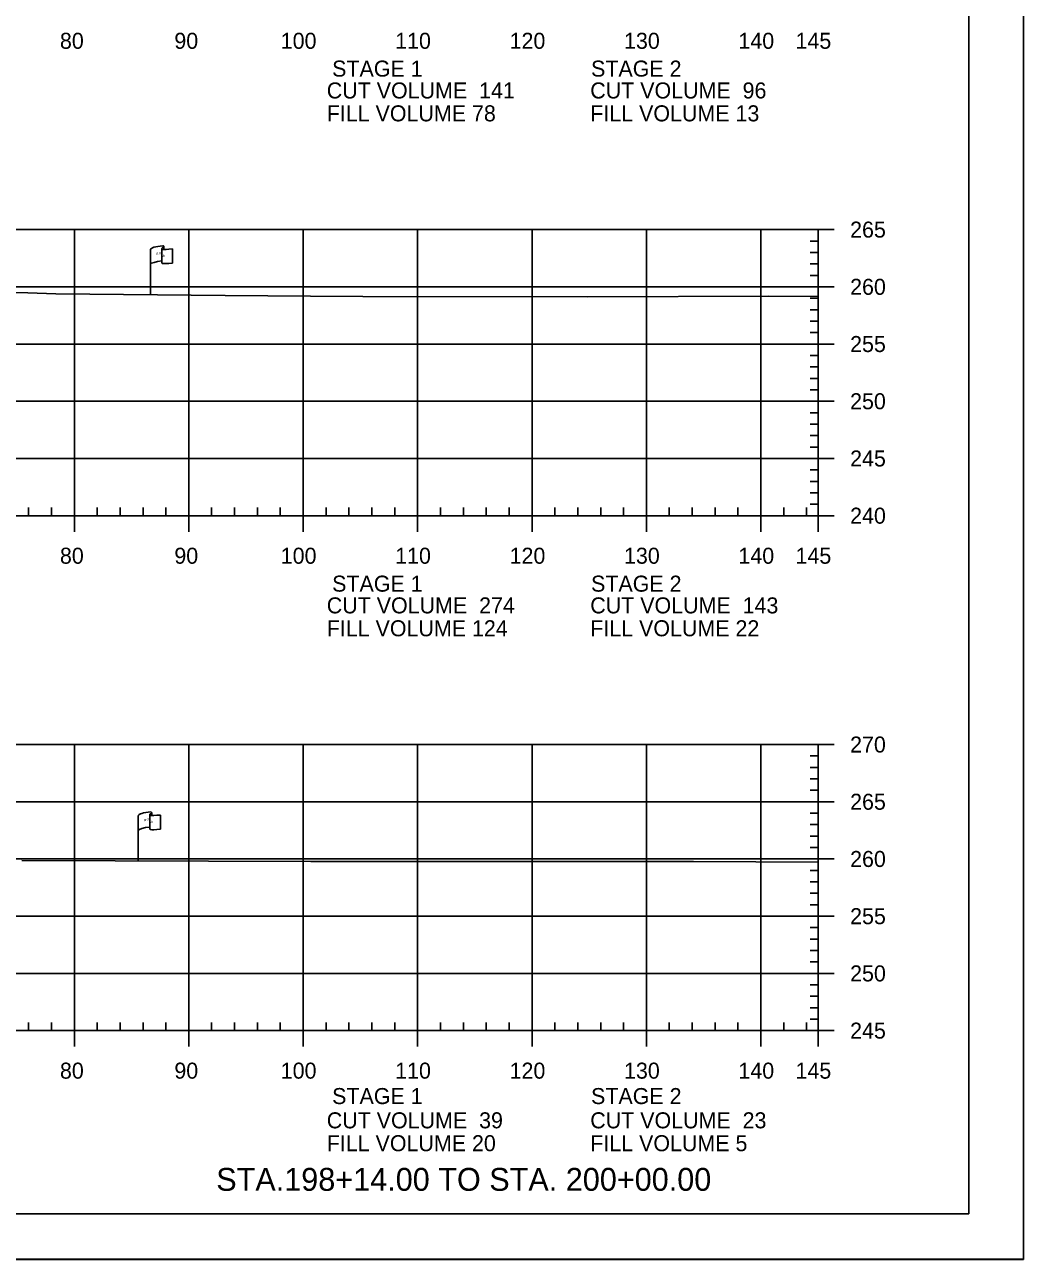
# Model space of a CAD drawing. Extents: x 1365647 to 1367999, y 387113 to 400173.
# Drawn here: x 1365969.7 to 1366057, y 389506.1 to 389614 of the extents above; entities that cross this region are included whole.
import ezdxf

# ---------------------------------------------------------------- set-up
doc = ezdxf.new("R2010")
doc.units = 0
for name, color, linetype in [('E_Existing ROW', 7, 'Continuous'), ('R_Axis', 7, 'Continuous'), ('R_Axis Annot', 7, 'Continuous'), ('R_Border', 7, 'Continuous'), ('R_Draft', 7, 'Continuous'), ('R_Exist Surface', 7, 'Continuous'), ('R_Grid', 7, 'Continuous'), ('R_No Plot', 7, 'Continuous')]:
    doc.layers.add(name, color=color, linetype=linetype)

msp = doc.modelspace()

# ---------------------------------------------------------------- linework, layer by layer
at = {"layer": 'E_Existing ROW'}
for p, q in [((1365980.74, 389590.4), (1365980.74, 389594.36)), ((1365981.74, 389594.45), (1365981.74, 389594.44)), ((1365981.74, 389594.44), (1365981.74, 389593.21)), ((1365981.91, 389594.61), (1365981.91, 389594.37)), ((1365982.68, 389594.41), (1365982.68, 389593.17)), ((1365979.68, 389540.93), (1365979.68, 389544.88)), ((1365980.68, 389544.98), (1365980.68, 389544.96)), ((1365980.68, 389544.96), (1365980.68, 389543.74)), ((1365980.85, 389545.13), (1365980.85, 389544.89)), ((1365981.61, 389544.94), (1365981.61, 389543.7))]:
    msp.add_line(p, q, dxfattribs=at)
for centre, radius, start, end in [((1365981.82, 389594.45), 0.078, 88.6458, 274.2828), ((1365981.83, 389594.61), 0.0783, 263.0712, 93.9564), ((1365981.82, 389593.21), 0.0783, 180, 273.9564), ((1365980.76, 389544.98), 0.078, 88.6458, 274.2828), ((1365980.77, 389545.13), 0.0783, 263.0712, 93.9564), ((1365980.76, 389543.74), 0.0783, 180, 273.9564)]:
    msp.add_arc(centre, radius, start, end, dxfattribs=at)
for centre, major_axis, ratio, start_param, end_param in [((1365982.33, 389594.4), (-1.58, -0.04), 0.19887, 5.030368, 6.283185), ((1365983.03, 389594.51), (-1.23, -0.13), 0.052933, 0.159456, 1.268315), ((1365982.32, 389593.08), (-1.58, -0.04), 0.19887, 5.083035, 6.194897), ((1365983.03, 389593.27), (-1.23, -0.13), 0.052933, 0.159456, 1.268315), ((1365981.27, 389544.93), (-1.58, -0.04), 0.19887, 5.030368, 6.283185), ((1365981.97, 389545.04), (-1.23, -0.13), 0.052933, 0.159456, 1.268315), ((1365981.26, 389543.61), (-1.58, -0.04), 0.19887, 5.083035, 6.194897), ((1365981.97, 389543.8), (-1.23, -0.13), 0.052933, 0.159456, 1.268315)]:
    msp.add_ellipse(centre, major_axis=major_axis, ratio=ratio, start_param=start_param, end_param=end_param, dxfattribs=at)
at = {"layer": 'R_Axis'}
for p, q in [((1366039.09, 389571.1), (1366039.09, 389596.1)), ((1366040.49, 389596.1), (1366039.09, 389596.1)), ((1366039.09, 389595.1), (1366038.39, 389595.1)), ((1366039.09, 389594.1), (1366038.39, 389594.1)), ((1366039.09, 389593.1), (1366038.39, 389593.1)), ((1366039.09, 389592.1), (1366038.39, 389592.1)), ((1366039.09, 389590.1), (1366038.39, 389590.1)), ((1366040.49, 389591.1), (1366039.09, 389591.1)), ((1366039.09, 389589.1), (1366038.39, 389589.1)), ((1366039.09, 389588.1), (1366038.39, 389588.1)), ((1366039.09, 389587.1), (1366038.39, 389587.1)), ((1366040.49, 389586.1), (1366039.09, 389586.1)), ((1366039.09, 389585.1), (1366038.39, 389585.1)), ((1366039.09, 389584.1), (1366038.39, 389584.1)), ((1366039.09, 389583.1), (1366038.39, 389583.1)), ((1366039.09, 389582.1), (1366038.39, 389582.1)), ((1366040.49, 389581.1), (1366039.09, 389581.1)), ((1366039.09, 389580.1), (1366038.39, 389580.1)), ((1366039.09, 389579.1), (1366038.39, 389579.1)), ((1366039.09, 389578.1), (1366038.39, 389578.1)), ((1366039.09, 389577.1), (1366038.39, 389577.1)), ((1366040.49, 389576.1), (1366039.09, 389576.1)), ((1366039.09, 389575.1), (1366038.39, 389575.1)), ((1366039.09, 389574.1), (1366038.39, 389574.1)), ((1366039.09, 389573.1), (1366038.39, 389573.1)), ((1365970.09, 389571.1), (1365970.09, 389571.8)), ((1365972.09, 389571.1), (1365972.09, 389571.8)), ((1365976.09, 389571.1), (1365976.09, 389571.8)), ((1365978.09, 389571.1), (1365978.09, 389571.8)), ((1365980.09, 389571.1), (1365980.09, 389571.8)), ((1365982.09, 389571.1), (1365982.09, 389571.8)), ((1365986.09, 389571.1), (1365986.09, 389571.8)), ((1365988.09, 389571.1), (1365988.09, 389571.8)), ((1365990.09, 389571.1), (1365990.09, 389571.8)), ((1365992.09, 389571.1), (1365992.09, 389571.8)), ((1365996.09, 389571.1), (1365996.09, 389571.8)), ((1365998.09, 389571.1), (1365998.09, 389571.8)), ((1366000.09, 389571.1), (1366000.09, 389571.8)), ((1366002.09, 389571.1), (1366002.09, 389571.8)), ((1366006.09, 389571.1), (1366006.09, 389571.8)), ((1366008.09, 389571.1), (1366008.09, 389571.8)), ((1366010.09, 389571.1), (1366010.09, 389571.8)), ((1366012.09, 389571.1), (1366012.09, 389571.8)), ((1366016.09, 389571.1), (1366016.09, 389571.8)), ((1366018.09, 389571.1), (1366018.09, 389571.8)), ((1366020.09, 389571.1), (1366020.09, 389571.8)), ((1366022.09, 389571.1), (1366022.09, 389571.8)), ((1366026.09, 389571.1), (1366026.09, 389571.8)), ((1366028.09, 389571.1), (1366028.09, 389571.8)), ((1366030.09, 389571.1), (1366030.09, 389571.8)), ((1366032.09, 389571.1), (1366032.09, 389571.8)), ((1366036.09, 389571.1), (1366036.09, 389571.8)), ((1366038.09, 389571.1), (1366038.09, 389571.8)), ((1366039.09, 389572.1), (1366038.39, 389572.1)), ((1365749.09, 389571.1), (1366039.09, 389571.1)), ((1365974.09, 389569.7), (1365974.09, 389571.1)), ((1365984.09, 389569.7), (1365984.09, 389571.1)), ((1365994.09, 389569.7), (1365994.09, 389571.1)), ((1366004.09, 389569.7), (1366004.09, 389571.1)), ((1366014.09, 389569.7), (1366014.09, 389571.1)), ((1366024.09, 389569.7), (1366024.09, 389571.1)), ((1366034.09, 389569.7), (1366034.09, 389571.1)), ((1366039.09, 389569.7), (1366039.09, 389571.1)), ((1366040.49, 389571.1), (1366039.09, 389571.1)), ((1366039.09, 389526.1), (1366039.09, 389551.1)), ((1366040.49, 389551.1), (1366039.09, 389551.1)), ((1366039.09, 389550.1), (1366038.39, 389550.1)), ((1366039.09, 389549.1), (1366038.39, 389549.1)), ((1366039.09, 389548.1), (1366038.39, 389548.1)), ((1366039.09, 389547.1), (1366038.39, 389547.1)), ((1366040.49, 389546.1), (1366039.09, 389546.1)), ((1366039.09, 389545.1), (1366038.39, 389545.1)), ((1366039.09, 389544.1), (1366038.39, 389544.1)), ((1366039.09, 389543.1), (1366038.39, 389543.1)), ((1366039.09, 389542.1), (1366038.39, 389542.1)), ((1366040.49, 389541.1), (1366039.09, 389541.1)), ((1366039.09, 389540.1), (1366038.39, 389540.1)), ((1366039.09, 389539.1), (1366038.39, 389539.1)), ((1366039.09, 389538.1), (1366038.39, 389538.1)), ((1366039.09, 389537.1), (1366038.39, 389537.1)), ((1366040.49, 389536.1), (1366039.09, 389536.1)), ((1366039.09, 389535.1), (1366038.39, 389535.1)), ((1366039.09, 389534.1), (1366038.39, 389534.1)), ((1366039.09, 389533.1), (1366038.39, 389533.1)), ((1366039.09, 389532.1), (1366038.39, 389532.1)), ((1366040.49, 389531.1), (1366039.09, 389531.1)), ((1366039.09, 389530.1), (1366038.39, 389530.1)), ((1366039.09, 389529.1), (1366038.39, 389529.1)), ((1366039.09, 389528.1), (1366038.39, 389528.1)), ((1365970.09, 389526.1), (1365970.09, 389526.8)), ((1365972.09, 389526.1), (1365972.09, 389526.8)), ((1365976.09, 389526.1), (1365976.09, 389526.8)), ((1365978.09, 389526.1), (1365978.09, 389526.8)), ((1365980.09, 389526.1), (1365980.09, 389526.8)), ((1365982.09, 389526.1), (1365982.09, 389526.8)), ((1365986.09, 389526.1), (1365986.09, 389526.8)), ((1365988.09, 389526.1), (1365988.09, 389526.8)), ((1365990.09, 389526.1), (1365990.09, 389526.8)), ((1365992.09, 389526.1), (1365992.09, 389526.8)), ((1365996.09, 389526.1), (1365996.09, 389526.8)), ((1365998.09, 389526.1), (1365998.09, 389526.8)), ((1366000.09, 389526.1), (1366000.09, 389526.8)), ((1366002.09, 389526.1), (1366002.09, 389526.8)), ((1366006.09, 389526.1), (1366006.09, 389526.8)), ((1366008.09, 389526.1), (1366008.09, 389526.8)), ((1366010.09, 389526.1), (1366010.09, 389526.8)), ((1366012.09, 389526.1), (1366012.09, 389526.8)), ((1366016.09, 389526.1), (1366016.09, 389526.8)), ((1366018.09, 389526.1), (1366018.09, 389526.8)), ((1366020.09, 389526.1), (1366020.09, 389526.8)), ((1366022.09, 389526.1), (1366022.09, 389526.8)), ((1366026.09, 389526.1), (1366026.09, 389526.8)), ((1366028.09, 389526.1), (1366028.09, 389526.8)), ((1366030.09, 389526.1), (1366030.09, 389526.8)), ((1366032.09, 389526.1), (1366032.09, 389526.8)), ((1366036.09, 389526.1), (1366036.09, 389526.8)), ((1366038.09, 389526.1), (1366038.09, 389526.8)), ((1366039.09, 389527.1), (1366038.39, 389527.1)), ((1365749.09, 389526.1), (1366039.09, 389526.1)), ((1365974.09, 389524.7), (1365974.09, 389526.1)), ((1365984.09, 389524.7), (1365984.09, 389526.1)), ((1365994.09, 389524.7), (1365994.09, 389526.1)), ((1366004.09, 389524.7), (1366004.09, 389526.1)), ((1366014.09, 389524.7), (1366014.09, 389526.1)), ((1366024.09, 389524.7), (1366024.09, 389526.1)), ((1366034.09, 389524.7), (1366034.09, 389526.1)), ((1366039.09, 389524.7), (1366039.09, 389526.1)), ((1366040.49, 389526.1), (1366039.09, 389526.1))]:
    msp.add_line(p, q, dxfattribs=at)
at = {"layer": 'R_Border'}
for q in [(1366052.27, 389715.56), (1365736.09, 389510.1)]:
    msp.add_line((1366052.27, 389510.1), q, dxfattribs=at)
at = {"layer": 'R_Exist Surface'}
for points in [[(1365964.2, 389590.68), (1365970.02, 389590.56), (1365972.48, 389590.49), (1365987.28, 389590.34), (1365994.72, 389590.27), (1365999.29, 389590.26), (1366018.98, 389590.23), (1366034.8, 389590.27), (1366039.09, 389590.25)], [(1365969.49, 389540.96), (1365985.82, 389540.91), (1365994.76, 389540.88), (1365996.63, 389540.89), (1366018.52, 389540.88), (1366028.21, 389540.88), (1366039.09, 389540.83)]]:
    msp.add_lwpolyline(points, dxfattribs=at)
at = {"layer": 'R_Grid'}
for p, q in [((1365749.09, 389596.1), (1366039.09, 389596.1)), ((1365974.09, 389571.1), (1365974.09, 389596.1)), ((1365984.09, 389571.1), (1365984.09, 389596.1)), ((1365994.09, 389571.1), (1365994.09, 389596.1)), ((1366004.09, 389571.1), (1366004.09, 389596.1)), ((1366014.09, 389571.1), (1366014.09, 389596.1)), ((1366024.09, 389571.1), (1366024.09, 389596.1)), ((1366034.09, 389571.1), (1366034.09, 389596.1)), ((1366039.09, 389571.1), (1366039.09, 389596.1)), ((1365749.09, 389591.1), (1366039.09, 389591.1)), ((1365749.09, 389586.1), (1366039.09, 389586.1)), ((1365749.09, 389581.1), (1366039.09, 389581.1)), ((1365749.09, 389576.1), (1366039.09, 389576.1)), ((1365749.09, 389571.1), (1366039.09, 389571.1)), ((1365749.09, 389551.1), (1366039.09, 389551.1)), ((1365974.09, 389526.1), (1365974.09, 389551.1)), ((1365984.09, 389526.1), (1365984.09, 389551.1)), ((1365994.09, 389526.1), (1365994.09, 389551.1)), ((1366004.09, 389526.1), (1366004.09, 389551.1)), ((1366014.09, 389526.1), (1366014.09, 389551.1)), ((1366024.09, 389526.1), (1366024.09, 389551.1)), ((1366034.09, 389526.1), (1366034.09, 389551.1)), ((1366039.09, 389526.1), (1366039.09, 389551.1)), ((1365749.09, 389546.1), (1366039.09, 389546.1)), ((1365749.09, 389541.1), (1366039.09, 389541.1)), ((1365749.09, 389536.1), (1366039.09, 389536.1)), ((1365749.09, 389531.1), (1366039.09, 389531.1)), ((1365749.09, 389526.1), (1366039.09, 389526.1))]:
    msp.add_line(p, q, dxfattribs=at)
at = {"layer": 'R_No Plot'}
msp.add_line((1365723.69, 389506.12), (1366057.03, 389506.12), dxfattribs=at)
msp.add_lwpolyline([(1365723.69, 389719.45), (1366057.03, 389719.45), (1366057.03, 389506.11), (1365723.69, 389506.11)], close=True, dxfattribs=at)

# ---------------------------------------------------------------- texts
at = {"layer": 'E_Existing ROW'}
for s, height, rotation, p in [('DWB 11-9-07', 0.001, 90, (1365981.91, 389594.37)), ('R ', 0.2, 9.9884, (1365981.26, 389593.86)), (' O', 0.2, 9.9884, (1365981.41, 389593.9)), ('W', 0.2, 351.1788, (1365981.74, 389593.73)), ('DWB 11-9-07', 0.001, 5.0717, (1365982.67, 389593.17)), ('DWB 11-9-07', 0.001, 90, (1365980.74, 389590.4)), ('DWB 11-9-07', 0.001, 90, (1365980.85, 389544.89)), ('R ', 0.2, 9.9884, (1365980.2, 389544.38)), (' O', 0.2, 9.9884, (1365980.35, 389544.43)), ('W', 0.2, 351.1788, (1365980.68, 389544.26)), ('DWB 11-9-07', 0.001, 5.0717, (1365981.6, 389543.7)), ('DWB 11-9-07', 0.001, 90, (1365979.68, 389540.93))]:
    msp.add_text(s, height=height, rotation=rotation, dxfattribs=at).set_placement(p)
at = {"layer": 'R_Axis Annot'}
for s, p in [('80', (1365972.83, 389611.9)), ('90', (1365982.83, 389611.9)), ('100', (1365992.13, 389611.9)), ('110', (1366002.13, 389611.9)), ('120', (1366012.13, 389611.9)), ('130', (1366022.13, 389611.9)), ('140', (1366032.13, 389611.9)), ('145', (1366037.12, 389611.9)), ('STAGE 1', (1365996.62, 389609.47)), ('STAGE 2', (1366019.25, 389609.47)), ('CUT VOLUME  141', (1365996.15, 389607.56)), ('CUT VOLUME  96', (1366019.18, 389607.56)), ('FILL VOLUME 78', (1365996.15, 389605.56)), ('FILL VOLUME 13', (1366019.18, 389605.56)), ('265', (1366041.89, 389595.4)), ('260', (1366041.89, 389590.4)), ('255', (1366041.89, 389585.4)), ('250', (1366041.89, 389580.4)), ('245', (1366041.89, 389575.4)), ('240', (1366041.89, 389570.4)), ('80', (1365972.83, 389566.9)), ('90', (1365982.83, 389566.9)), ('100', (1365992.13, 389566.9)), ('110', (1366002.13, 389566.9)), ('120', (1366012.13, 389566.9)), ('130', (1366022.13, 389566.9)), ('140', (1366032.13, 389566.9)), ('145', (1366037.12, 389566.9)), ('STAGE 1', (1365996.62, 389564.46)), ('STAGE 2', (1366019.25, 389564.46)), ('CUT VOLUME  274', (1365996.15, 389562.56)), ('CUT VOLUME  143', (1366019.18, 389562.56)), ('FILL VOLUME 124', (1365996.15, 389560.56)), ('FILL VOLUME 22', (1366019.18, 389560.56)), ('270', (1366041.89, 389550.4)), ('265', (1366041.89, 389545.4)), ('260', (1366041.89, 389540.4)), ('255', (1366041.89, 389535.4)), ('250', (1366041.89, 389530.4)), ('245', (1366041.89, 389525.4)), ('80', (1365972.83, 389521.9)), ('90', (1365982.83, 389521.9)), ('100', (1365992.13, 389521.9)), ('110', (1366002.13, 389521.9)), ('120', (1366012.13, 389521.9)), ('130', (1366022.13, 389521.9)), ('140', (1366032.13, 389521.9)), ('145', (1366037.12, 389521.9)), ('STAGE 1', (1365996.62, 389519.68)), ('STAGE 2', (1366019.25, 389519.68)), ('CUT VOLUME  39', (1365996.15, 389517.56)), ('CUT VOLUME  23', (1366019.18, 389517.56)), ('FILL VOLUME 20', (1365996.15, 389515.56)), ('FILL VOLUME 5', (1366019.18, 389515.56))]:
    msp.add_text(s, height=1.4, dxfattribs=at).set_placement(p)
at = {"layer": 'R_Draft'}
msp.add_text('STA.198+14.00 TO STA. 200+00.00', height=2, dxfattribs=at).set_placement((1365986.49, 389512.1))

doc.saveas('drawing.dxf')
